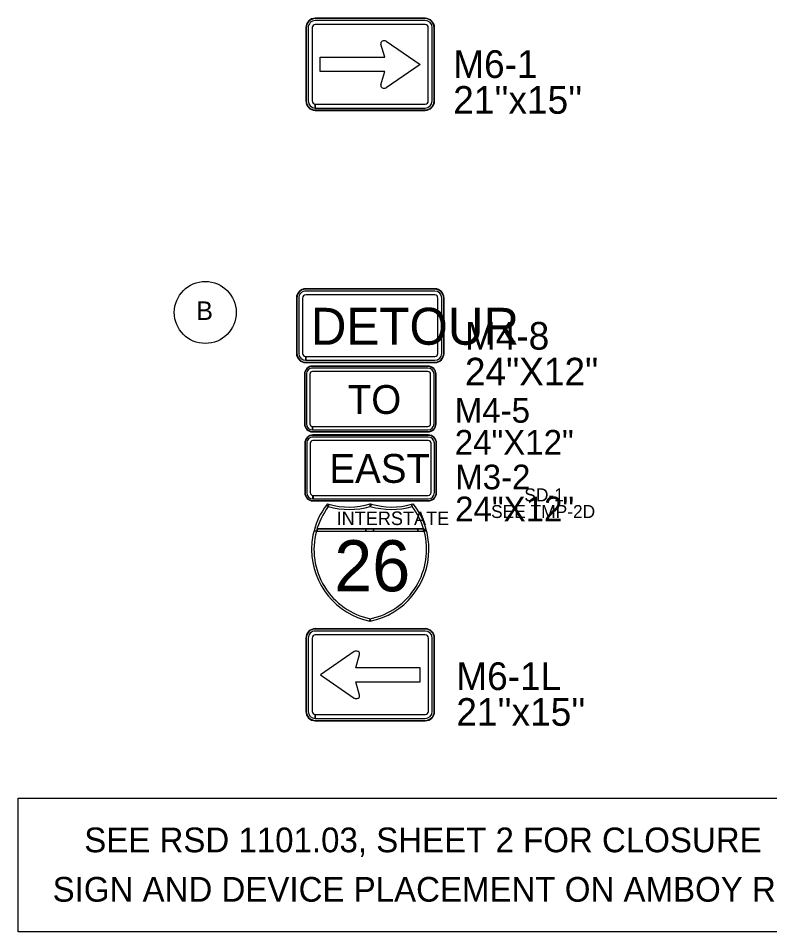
# Model space of a CAD drawing. Extents: x 886234 to 968767, y 455416 to 684046.
# Drawn here: x 915256 to 919819, y 524542 to 530086 of the extents above; entities that cross this region are included whole.
import ezdxf

# ---------------------------------------------------------------- set-up
doc = ezdxf.new("R2010")
doc.units = 0
for name, color, linetype in [('TC DEV SIGN BLACK 239', 7, 'Continuous'), ('TC DEV SIGN BLACK ZERO', 7, 'Continuous'), ('TC DEV SIGN ORANGE', 7, 'Continuous'), ('TC DEV SIGN WHITE', 7, 'Continuous'), ('TC LABEL TEXT', 7, 'Continuous')]:
    doc.layers.add(name, color=color, linetype=linetype)

msp = doc.modelspace()

# ---------------------------------------------------------------- linework, layer by layer
at = {"layer": 'TC DEV SIGN BLACK 239'}
for p, q in [((917727.2, 530072), (917059.3, 530072)), ((917727.2, 530048.3), (917059.3, 530048.3)), ((917016.7, 530029.4), (917016.7, 529584.1)), ((917040.4, 530029.4), (917040.3, 529584.1)), ((917746.1, 529584.1), (917746.1, 530029.4)), ((917769.7, 529584.1), (917769.7, 530029.4)), ((917481.8, 529849.4), (917458.7, 529930)), ((917490.7, 529947.2), (917696, 529805.8)), ((917090, 529763.7), (917090, 529849.4)), ((917090, 529849.4), (917481.8, 529849.4)), ((917481.8, 529763.7), (917090, 529763.7)), ((917458.7, 529681.7), (917481.8, 529763.7)), ((917696, 529805.8), (917490.7, 529664.4)), ((917059.3, 529541.5), (917059.3, 529565.2)), ((917059.5, 529565.2), (917727.1, 529565.2)), ((917059.5, 529565.2), (917059.5, 529541.5)), ((917059.5, 529541.5), (917727.1, 529541.5)), ((917745.8, 527544.4), (917045.7, 527544.4)), ((917008.2, 527506.9), (917008.2, 527206.9)), ((917029.1, 527506.9), (917029.1, 527206.9)), ((917745.8, 527523.6), (917045.7, 527523.6)), ((917762.5, 527206.9), (917762.5, 527506.9)), ((917783.3, 527206.9), (917783.3, 527506.9)), ((917045.7, 527169.4), (917045.7, 527190.2)), ((917045.9, 527190.2), (917745.8, 527190.2)), ((917045.9, 527190.2), (917045.9, 527169.4)), ((917045.9, 527169.4), (917745.8, 527169.4)), ((917017.1, 526324.6), (917017, 525879.3)), ((917040.7, 526324.6), (917040.7, 525879.3)), ((917727.5, 526367.1), (917059.7, 526367.1)), ((917727.5, 526343.5), (917059.7, 526343.5)), ((917746.4, 525879.3), (917746.4, 526324.6)), ((917770.1, 525879.3), (917770.1, 526324.6)), ((917296.1, 526242.4), (917090.8, 526101)), ((917305, 526144.6), (917328.2, 526225.2)), ((917090.8, 526101), (917296.1, 525959.6)), ((917696.8, 526144.6), (917305, 526144.6)), ((917696.8, 526058.9), (917696.8, 526144.6)), ((917328.2, 525976.8), (917305, 526058.9)), ((917305, 526058.9), (917696.8, 526058.9)), ((917059.6, 525836.7), (917059.6, 525860.3)), ((917059.9, 525860.3), (917727.5, 525860.3)), ((917059.9, 525860.3), (917059.9, 525836.7)), ((917059.9, 525836.7), (917727.5, 525836.7))]:
    msp.add_line(p, q, dxfattribs=at)
for centre, major_axis, ratio, start_param, end_param in [((917059.3, 530029.4), (42.6, 0), 0.999865, 1.570796, 3.141593), ((917059.3, 530029.4), (18.9, 0), 0.999865, 1.570796, 3.141593), ((917727.2, 530029.4), (42.6, 0), 0.999865, 0, 1.570796), ((917727.2, 530029.4), (18.9, 0), 0.999865, 0, 1.570796), ((917478.8, 529934.7), (21.1, 0), 0.720018, 0.96961, 3.452569), ((917478.8, 529677), (21.1, 0), 0.720018, 2.830617, 5.313577), ((917059.3, 529584.1), (42.6, 0), 0.999865, 3.141593, 4.712389), ((917059.3, 529584.1), (18.9, 0), 0.999865, 3.141593, 4.712389), ((917727.1, 529584.1), (42.6, 0), 0.999865, 4.712389, 6.283185), ((917727.1, 529584.1), (18.9, 0), 0.999865, 4.712389, 6.283185), ((917045.7, 527506.9), (37.5, 0), 0.999865, 1.570796, 3.141593), ((917745.8, 527506.9), (37.5, 0), 0.999865, 0, 1.570796), ((917045.7, 527506.9), (16.7, 0), 0.999865, 1.570796, 3.141593), ((917745.8, 527506.9), (16.7, 0), 0.999865, 0, 1.570796), ((917045.7, 527206.9), (37.5, 0), 0.999865, 3.141593, 4.712389), ((917045.7, 527206.9), (16.7, 0), 0.999865, 3.141593, 4.712389), ((917745.8, 527206.9), (37.5, 0), 0.999865, 4.712389, 6.283185), ((917745.8, 527206.9), (16.7, 0), 0.999865, 4.712389, 6.283185), ((917059.7, 526324.6), (42.6, 0), 0.999865, 1.570796, 3.141593), ((917059.7, 526324.6), (18.9, 0), 0.999865, 1.570796, 3.141593), ((917727.5, 526324.6), (42.6, 0), 0.999865, 0, 1.570796), ((917727.5, 526324.6), (18.9, 0), 0.999865, 0, 1.570796), ((917308, 526229.8), (-21.1, 0), 0.720018, 2.830616, 5.313575), ((917308, 525972.2), (-21.1, 0), 0.720018, 0.969609, 3.452568), ((917059.6, 525879.3), (42.6, 0), 0.999865, 3.141593, 4.712389), ((917059.6, 525879.3), (18.9, 0), 0.999865, 3.141593, 4.712389), ((917727.5, 525879.3), (42.6, 0), 0.999865, 4.712389, 6.283185), ((917727.5, 525879.3), (18.9, 0), 0.999865, 4.712389, 6.283185)]:
    msp.add_ellipse(centre, major_axis=major_axis, ratio=ratio, start_param=start_param, end_param=end_param, dxfattribs=at)
at = {"layer": 'TC DEV SIGN BLACK ZERO'}
for p, q in [((917727.2, 530086.2), (917059.3, 530086.2)), ((917059.3, 530083.8), (917059.3, 530083.8)), ((917727.2, 530083.8), (917059.3, 530083.8)), ((917727.2, 530083.8), (917727.2, 530083.8)), ((917002.5, 530029.4), (917002.5, 529584.1)), ((917004.8, 530029.4), (917004.8, 529584.1)), ((917004.8, 530029.4), (917004.9, 530029.4)), ((917781.6, 530029.4), (917781.6, 530029.4)), ((917781.6, 529584.1), (917781.6, 530029.4)), ((917783.9, 529584.1), (917783.9, 530029.4)), ((917004.8, 529584.1), (917004.8, 529584.1)), ((917781.6, 529584.1), (917781.6, 529584.1)), ((917059.3, 529527.3), (917059.3, 529529.7)), ((917059.3, 529529.7), (917059.3, 529529.7)), ((917059.3, 529529.7), (917727.1, 529529.7)), ((917059.3, 529529.7), (917059.3, 529527.3)), ((917059.3, 529527.3), (917727.1, 529527.3)), ((917727.1, 529529.7), (917727.1, 529529.7)), ((917785.6, 528444.2), (917001.5, 528444.2)), ((917001.5, 528441.9), (917001.5, 528441.9)), ((917785.6, 528441.9), (917001.5, 528441.9)), ((917785.6, 528430.2), (917001.5, 528430.2)), ((917785.6, 528441.9), (917785.6, 528441.9)), ((916945.5, 528388.2), (916945.5, 528052.2)), ((916947.8, 528388.2), (916947.8, 528052.2)), ((916947.8, 528388.2), (916947.8, 528388.2)), ((916959.5, 528388.2), (916959.5, 528052.2)), ((916982.8, 528388.2), (916982.8, 528052.2)), ((917785.6, 528406.9), (917001.5, 528406.9)), ((917804.3, 528052.2), (917804.3, 528388.2)), ((917827.6, 528052.2), (917827.6, 528388.2)), ((917839.3, 528388.2), (917839.3, 528388.2)), ((917839.3, 528052.2), (917839.3, 528388.2)), ((917841.6, 528052.2), (917841.6, 528388.2)), ((916947.8, 528052.2), (916947.8, 528052.2)), ((917839.3, 528052.2), (917839.3, 528052.2)), ((917001.5, 528010.2), (917001.5, 528033.6)), ((917001.5, 527996.2), (917001.5, 527998.6)), ((917001.5, 527998.6), (917001.5, 527998.6)), ((917001.5, 527998.6), (917785.6, 527998.6)), ((917001.5, 527998.6), (917001.5, 527996.2)), ((917001.5, 527996.2), (917785.6, 527996.2)), ((917001.7, 528033.6), (917785.6, 528033.6)), ((917001.7, 528033.6), (917001.7, 528010.2)), ((917001.7, 528010.2), (917785.6, 528010.2)), ((917785.6, 527998.6), (917785.6, 527998.6)), ((917743.6, 527975.4), (917043.5, 527975.4)), ((917043.5, 527973.3), (917043.5, 527973.3)), ((917743.6, 527973.3), (917043.5, 527973.3)), ((917743.6, 527962.9), (917043.5, 527962.9)), ((917743.6, 527942.1), (917043.5, 527942.1)), ((917743.6, 527973.3), (917743.6, 527973.3)), ((916993.5, 527925.4), (916993.5, 527625.4)), ((916995.6, 527925.4), (916995.6, 527625.4)), ((916995.6, 527925.4), (916995.6, 527925.4)), ((917006, 527925.4), (917006, 527625.4)), ((917026.8, 527925.4), (917026.8, 527625.4)), ((917760.3, 527625.4), (917760.3, 527925.4)), ((917781.1, 527625.4), (917781.1, 527925.4)), ((917791.5, 527925.4), (917791.5, 527925.4)), ((917791.5, 527625.4), (917791.5, 527925.4)), ((917793.6, 527625.4), (917793.6, 527925.4)), ((916995.6, 527625.4), (916995.6, 527625.4)), ((917043.5, 527587.9), (917043.5, 527608.7)), ((917043.7, 527608.7), (917743.6, 527608.7)), ((917043.7, 527608.7), (917043.7, 527587.9)), ((917791.5, 527625.4), (917791.5, 527625.4)), ((917043.5, 527575.4), (917043.5, 527577.5)), ((917043.5, 527577.5), (917043.5, 527577.5)), ((917043.5, 527577.5), (917743.6, 527577.5)), ((917043.5, 527577.5), (917043.5, 527575.4)), ((917043.5, 527575.4), (917743.6, 527575.4)), ((917043.7, 527587.9), (917743.6, 527587.9)), ((917745.8, 527556.9), (917045.7, 527556.9)), ((917045.7, 527554.8), (917045.7, 527554.8)), ((917745.8, 527554.8), (917045.7, 527554.8)), ((917743.6, 527577.5), (917743.6, 527577.5)), ((917745.8, 527554.8), (917745.8, 527554.8)), ((916995.7, 527506.9), (916995.7, 527206.9)), ((916997.8, 527506.9), (916997.8, 527206.9)), ((916997.8, 527506.9), (916997.8, 527506.9)), ((917793.8, 527506.9), (917793.8, 527506.9)), ((917793.8, 527206.9), (917793.8, 527506.9)), ((917795.8, 527206.9), (917795.8, 527506.9)), ((916997.8, 527206.9), (916997.8, 527206.9)), ((917793.8, 527206.9), (917793.8, 527206.9)), ((917045.7, 527156.9), (917045.7, 527159)), ((917045.7, 527159), (917045.7, 527159)), ((917045.8, 527159), (917745.8, 527159)), ((917045.8, 527159), (917045.8, 527156.9)), ((917045.8, 527156.9), (917745.8, 527156.9)), ((917745.8, 527159), (917745.8, 527159)), ((917393.9, 527124.7), (917393.6, 527139.1)), ((917644.3, 527136.3), (917648.3, 527122)), ((917366.4, 526987.2), (917070.5, 526987.2)), ((917413.3, 526987.2), (917366.4, 526987.2)), ((917681.7, 526987.2), (917413.3, 526987.2)), ((917716.7, 526987.2), (917681.7, 526987.2)), ((917070.5, 526972.3), (917366.4, 526972.3)), ((917366.4, 526972.3), (917413.3, 526972.3)), ((917413.3, 526972.3), (917681.7, 526972.3)), ((917681.7, 526972.3), (917716.7, 526972.3)), ((917037.3, 526865.1), (917037.3, 526860.7)), ((917749.8, 526860.6), (917749.8, 526865.2)), ((917727.5, 526381.3), (917059.7, 526381.3)), ((917059.7, 526379), (917059.7, 526379)), ((917727.5, 526379), (917059.7, 526379)), ((917727.5, 526379), (917727.5, 526379)), ((917002.9, 526324.6), (917002.8, 525879.3)), ((917005.2, 526324.6), (917005.2, 525879.3)), ((917005.2, 526324.6), (917005.2, 526324.6)), ((917781.9, 526324.6), (917782, 526324.6)), ((917781.9, 525879.3), (917782, 526324.6)), ((917784.3, 525879.3), (917784.3, 526324.6)), ((917005.2, 525879.3), (917005.2, 525879.3)), ((917781.9, 525879.3), (917781.9, 525879.3)), ((917059.6, 525822.5), (917059.6, 525824.9)), ((917059.6, 525824.9), (917059.6, 525824.8)), ((917059.7, 525824.9), (917727.5, 525824.9)), ((917059.7, 525824.9), (917059.7, 525822.5)), ((917059.7, 525822.5), (917727.5, 525822.5)), ((917727.5, 525824.8), (917727.5, 525824.9))]:
    msp.add_line(p, q, dxfattribs=at)
for points in [[(917138.9, 527122), (917127, 527130.9)], [(917142.9, 527136.3), (917138.9, 527122)], [(917393.6, 527123.6), (917393.9, 527124.7)], [(917398.1, 527137.7), (917394, 527123.6)], [(917648.3, 527122), (917644.3, 527136.3)], [(917653.9, 527139.1), (917653.9, 527139.1), (917653.8, 527139.1)], [(917070.5, 526987.2), (917070.5, 526972.3)], [(917366.4, 526987.2), (917366.4, 526972.3)], [(917366.4, 526972.3), (917366.4, 526987.2)], [(917413.3, 526987.2), (917413.3, 526972.3)], [(917413.3, 526972.3), (917413.3, 526987.2)], [(917681.7, 526972.3), (917681.7, 526987.2)], [(917681.7, 526987.2), (917681.7, 526972.3)], [(917716.7, 526987.2), (917735.2, 526976.1)], [(917716.7, 526972.3), (917716.7, 526987.2)], [(917052, 526976.1), (917066.3, 526972.3)], [(917066.3, 526972.3), (917052, 526976.1)], [(917735.2, 526976.1), (917720.9, 526972.3)], [(917390.5, 526427.2), (917393.6, 526441.7)], [(917393.6, 526441.7), (917393.6, 526426.6)]]:
    msp.add_lwpolyline(points, dxfattribs=at)
for centre, radius, start, end in [((917482.7, 526862.9), 445.3, 142.9968, 165.2769), ((917482.7, 526862.9), 430.5, 142.9968, 165.2769), ((917263.5, 527565), 460.2, 254.2907, 286.4259), ((917263.5, 527565), 445.3, 254.2907, 286.9893), ((917523.9, 527564.3), 459.4, 253.5731, 285.7093), ((917523.7, 527565), 445.3, 253.6206, 285.7093), ((917523.7, 527565), 445.3, 285.7093, 286.9901), ((917304.5, 526862.9), 430.5, 16.7759, 37.0032), ((917304.5, 526862.9), 445.3, 14.7231, 38.3291), ((917482.7, 526862.9), 445.3, 165.2769, 179.7177), ((917480.5, 526861.6), 428.8, 165.0438, 258.3001), ((917306.6, 526861.6), 428.8, 281.7196, 14.964), ((917304.5, 526862.9), 445.3, 0.2997, 14.7231), ((917482.7, 526862.9), 445.3, 180.2823, 258.0591), ((917304.5, 526862.9), 445.3, 281.537, 359.7003), ((917304.5, 526862.9), 430.5, 281.9405, 281.9604)]:
    msp.add_arc(centre, radius, start, end, dxfattribs=at)
for centre, major_axis, start_param, end_param in [((917059.3, 530029.4), (56.8, 0), 1.570796, 3.141593), ((917059.3, 530029.4), (54.4, 0), 1.570796, 3.141593), ((917727.2, 530029.4), (56.8, 0), 0, 1.570796), ((917727.2, 530029.4), (54.4, 0), 0, 1.570796), ((917059.3, 529584.1), (56.8, 0), 3.141593, 4.712389), ((917059.3, 529584.1), (54.4, 0), 3.141593, 4.712389), ((917727.1, 529584.1), (56.8, 0), 4.712389, 6.283185), ((917727.1, 529584.1), (54.4, 0), 4.712389, 6.283185), ((917001.5, 528388.2), (56, 0), 1.570796, 3.141593), ((917001.5, 528388.2), (53.7, 0), 1.570796, 3.141593), ((917001.5, 528388.2), (42, 0), 1.570796, 3.141593), ((917785.6, 528388.2), (56, 0), 0, 1.570796), ((917785.6, 528388.2), (53.7, 0), 0, 1.570796), ((917785.6, 528388.2), (42, 0), 0, 1.570796), ((917001.5, 528388.2), (18.7, 0), 1.570796, 3.141593), ((917785.6, 528388.2), (18.7, 0), 0, 1.570796), ((917001.5, 528052.2), (56, 0), 3.141593, 4.712389), ((917001.5, 528052.2), (53.7, 0), 3.141593, 4.712389), ((917001.5, 528052.2), (42, 0), 3.141593, 4.712389), ((917001.5, 528052.2), (18.7, 0), 3.141593, 4.712389), ((917785.6, 528052.2), (42, 0), 4.712389, 6.283185), ((917785.6, 528052.2), (18.7, 0), 4.712389, 6.283185), ((917785.6, 528052.2), (56, 0), 4.712389, 6.283185), ((917785.6, 528052.2), (53.7, 0), 4.712389, 6.283185), ((917043.5, 527925.4), (50, 0), 1.570796, 3.141593), ((917043.5, 527925.4), (47.9, 0), 1.570796, 3.141593), ((917043.5, 527925.4), (37.5, 0), 1.570796, 3.141593), ((917043.5, 527925.4), (16.7, 0), 1.570796, 3.141593), ((917743.6, 527925.4), (50, 0), 0, 1.570796), ((917743.6, 527925.4), (47.9, 0), 0, 1.570796), ((917743.6, 527925.4), (37.5, 0), 0, 1.570796), ((917743.6, 527925.4), (16.7, 0), 0, 1.570796), ((917043.5, 527625.4), (50, 0), 3.141593, 4.712389), ((917043.5, 527625.4), (47.9, 0), 3.141593, 4.712389), ((917043.5, 527625.4), (37.5, 0), 3.141593, 4.712389), ((917043.5, 527625.4), (16.7, 0), 3.141593, 4.712389), ((917743.6, 527625.4), (37.5, 0), 4.712389, 6.283185), ((917743.6, 527625.4), (16.7, 0), 4.712389, 6.283185), ((917743.6, 527625.4), (50, 0), 4.712389, 6.283185), ((917743.6, 527625.4), (47.9, 0), 4.712389, 6.283185), ((917045.7, 527506.9), (50, 0), 1.570796, 3.141593), ((917045.7, 527506.9), (47.9, 0), 1.570796, 3.141593), ((917745.8, 527506.9), (50, 0), 0, 1.570796), ((917745.8, 527506.9), (47.9, 0), 0, 1.570796), ((917045.7, 527206.9), (50, 0), 3.141593, 4.712389), ((917045.7, 527206.9), (47.9, 0), 3.141593, 4.712389), ((917745.8, 527206.9), (50, 0), 4.712389, 6.283185), ((917745.8, 527206.9), (47.9, 0), 4.712389, 6.283185), ((917059.7, 526324.6), (56.8, 0), 1.570796, 3.141593), ((917059.7, 526324.6), (54.4, 0), 1.570796, 3.141593), ((917727.5, 526324.6), (56.8, 0), 0, 1.570796), ((917727.5, 526324.6), (54.4, 0), 0, 1.570796), ((917059.6, 525879.3), (56.8, 0), 3.141593, 4.712389), ((917059.6, 525879.3), (54.4, 0), 3.141593, 4.712389), ((917727.5, 525879.3), (56.8, 0), 4.712389, 6.283185), ((917727.5, 525879.3), (54.4, 0), 4.712389, 6.283185)]:
    msp.add_ellipse(centre, major_axis=major_axis, ratio=0.999865, start_param=start_param, end_param=end_param, dxfattribs=at)
at = {"layer": 'TC DEV SIGN ORANGE'}
for p, q in [((917785.6, 528444.2), (917001.5, 528444.2)), ((916945.5, 528388.2), (916945.5, 528052.2)), ((917841.6, 528052.2), (917841.6, 528388.2)), ((917001.5, 527996.2), (917785.6, 527996.2)), ((917743.6, 527975.4), (917043.5, 527975.4)), ((916993.5, 527925.4), (916993.5, 527625.4)), ((917793.6, 527625.4), (917793.6, 527925.4)), ((917043.5, 527575.4), (917743.6, 527575.4))]:
    msp.add_line(p, q, dxfattribs=at)
for centre, major_axis, start_param, end_param in [((917001.5, 528388.2), (56, 0), 1.570796, 3.141593), ((917785.6, 528388.2), (56, 0), 0, 1.570796), ((917001.5, 528052.2), (56, 0), 3.141593, 4.712389), ((917785.6, 528052.2), (56, 0), 4.712389, 6.283185), ((917043.5, 527925.4), (50, 0), 1.570796, 3.141593), ((917743.6, 527925.4), (50, 0), 0, 1.570796), ((917043.5, 527625.4), (50, 0), 3.141593, 4.712389), ((917743.6, 527625.4), (50, 0), 4.712389, 6.283185)]:
    msp.add_ellipse(centre, major_axis=major_axis, ratio=0.999865, start_param=start_param, end_param=end_param, dxfattribs=at)
at = {"layer": 'TC DEV SIGN WHITE'}
for p, q in [((917727.2, 530086.2), (917059.3, 530086.2)), ((917002.5, 530029.4), (917002.5, 529584.1)), ((917783.9, 529584.1), (917783.9, 530029.4)), ((917059.3, 529527.3), (917727.1, 529527.3)), ((917745.8, 527556.9), (917045.7, 527556.9)), ((916995.7, 527506.9), (916995.7, 527206.9)), ((917795.8, 527206.9), (917795.8, 527506.9)), ((917045.7, 527156.9), (917745.8, 527156.9)), ((917138.9, 527122), (917142.9, 527136.3)), ((917394, 527123.6), (917393.6, 527139.1)), ((917070.5, 526987.2), (917716.7, 526987.2)), ((917735.2, 526976.1), (917716.7, 526987.2)), ((917066.3, 526972.3), (917720.9, 526972.3)), ((917066.3, 526972.3), (917070.5, 526972.3)), ((917720.6, 526973.3), (917716.7, 526972.3)), ((917716.7, 526972.3), (917720.9, 526972.3)), ((917393.6, 526426.6), (917393.6, 526441.7)), ((917727.5, 526381.3), (917059.7, 526381.3)), ((917002.9, 526324.6), (917002.8, 525879.3)), ((917784.3, 525879.3), (917784.3, 526324.6)), ((917059.6, 525822.5), (917727.5, 525822.5))]:
    msp.add_line(p, q, dxfattribs=at)
for points in [[(917127, 527130.9), (917138.9, 527122)], [(917133.3, 527139.1), (917133.3, 527139.1), (917133.3, 527139.1)], [(917393.9, 527139), (917393.9, 527124.7), (917398.1, 527137.7)], [(917070.5, 526972.3), (917070.5, 526987.2)], [(917716.7, 526987.2), (917716.7, 526972.3), (917720.6, 526973.3), (917716.7, 526987.2)], [(917720.9, 526972.3), (917720.6, 526973.3)], [(917720.9, 526972.3), (917735.2, 526976.1)], [(917393.6, 526441.7), (917390.5, 526427.2), (917393.5, 526426.6)]]:
    msp.add_lwpolyline(points, dxfattribs=at)
for centre, radius, start, end in [((917482.7, 526862.9), 445.3, 141.6709, 142.9968), ((917263.5, 527565), 445.3, 253.0099, 254.2907), ((917523.7, 527565), 445.3, 253.0588, 253.6206), ((917482.7, 526862.9), 430.5, 163.2241, 165.2769), ((917304.5, 526862.9), 430.5, 14.7231, 16.7759), ((917482.7, 526862.9), 445.3, 258.458, 258.463), ((917304.5, 526862.9), 445.3, 281.5369590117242, 281.53700435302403)]:
    msp.add_arc(centre, radius, start, end, dxfattribs=at)
for centre, major_axis, start_param, end_param in [((917059.3, 530029.4), (56.8, 0), 1.570796, 3.141593), ((917727.2, 530029.4), (56.8, 0), 0, 1.570796), ((917059.3, 529584.1), (56.8, 0), 3.141593, 4.712389), ((917727.1, 529584.1), (56.8, 0), 4.712389, 6.283185), ((917045.7, 527506.9), (50, 0), 1.570796, 3.141593), ((917745.8, 527506.9), (50, 0), 0, 1.570796), ((917045.7, 527206.9), (50, 0), 3.141593, 4.712389), ((917745.8, 527206.9), (50, 0), 4.712389, 6.283185), ((917059.7, 526324.6), (56.8, 0), 1.570796, 3.141593), ((917727.5, 526324.6), (56.8, 0), 0, 1.570796), ((917059.6, 525879.3), (56.8, 0), 3.141593, 4.712389), ((917727.5, 525879.3), (56.8, 0), 4.712389, 6.283185)]:
    msp.add_ellipse(centre, major_axis=major_axis, ratio=0.999865, start_param=start_param, end_param=end_param, dxfattribs=at)
at = {"layer": 'TC LABEL TEXT'}
msp.add_lwpolyline([(915256.2, 525352), (920455.1, 525352), (920455.1, 524541.9), (915256.2, 524541.9)], close=True, dxfattribs=at)
msp.add_circle((916391.8, 528300.6), 188.1, dxfattribs=at)

# ---------------------------------------------------------------- texts
at = {"layer": 'TC DEV SIGN BLACK 239'}
msp.add_text('EAST', height=175, rotation=360, dxfattribs=at).set_placement((917145.2, 527266.4))
at = {"layer": 'TC DEV SIGN BLACK ZERO'}
for s, height, p in [('M6-1', 168, (917897.3, 529723.9)), ("21''x15''", 168, (917897.3, 529506.6)), ('M4-8', 168, (917968.4, 528074.7)), ('24"X12"', 168, (917968.4, 527857.4)), ('TO', 175, (917256.7, 527684.9)), ('M4-5', 150, (917906.6, 527631.4)), ('24"X12"', 150, (917906.6, 527437.4)), ('M3-2', 150, (917909, 527227)), ('24"X12"', 150, (917909, 527033)), ('INTERSTATE', 82.13, (917189.5, 527010.2)), ('26', 310.26, (917174.7, 526607.9)), ('M6-1L', 168, (917916.1, 526009.1)), ("21''x15''", 168, (917916.1, 525791.8))]:
    msp.add_text(s, height=height, rotation=360, dxfattribs=at).set_placement(p)
msp.add_text('DETOUR', height=224, dxfattribs=at).set_placement((917032.6, 528104.8))
at = {"layer": 'TC LABEL TEXT'}
for s, height, p in [('B', 112.5, (916337.7, 528255.2)), ('SD-1', 78.75, (918328.9, 527154)), ('SEE TMP-2D', 78.75, (918127.1, 527052.9)), ('SEE RSD 1101.03, SHEET 2 FOR CLOSURE ', 150, (915656.8, 525024.2)), ('SIGN AND DEVICE PLACEMENT ON AMBOY RD', 150, (915464.9, 524724.2))]:
    msp.add_text(s, height=height, dxfattribs=at).set_placement(p)

doc.saveas('drawing.dxf')
